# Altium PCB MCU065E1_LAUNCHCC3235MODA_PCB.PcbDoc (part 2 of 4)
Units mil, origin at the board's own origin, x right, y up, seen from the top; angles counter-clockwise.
Board outline 2300 x 4280 mil, 4 copper layers (TOP, GND, PWR, BOTTOM), stack 62 mil thick; 300 components, 199 nets, 970 pads, 475 vias.
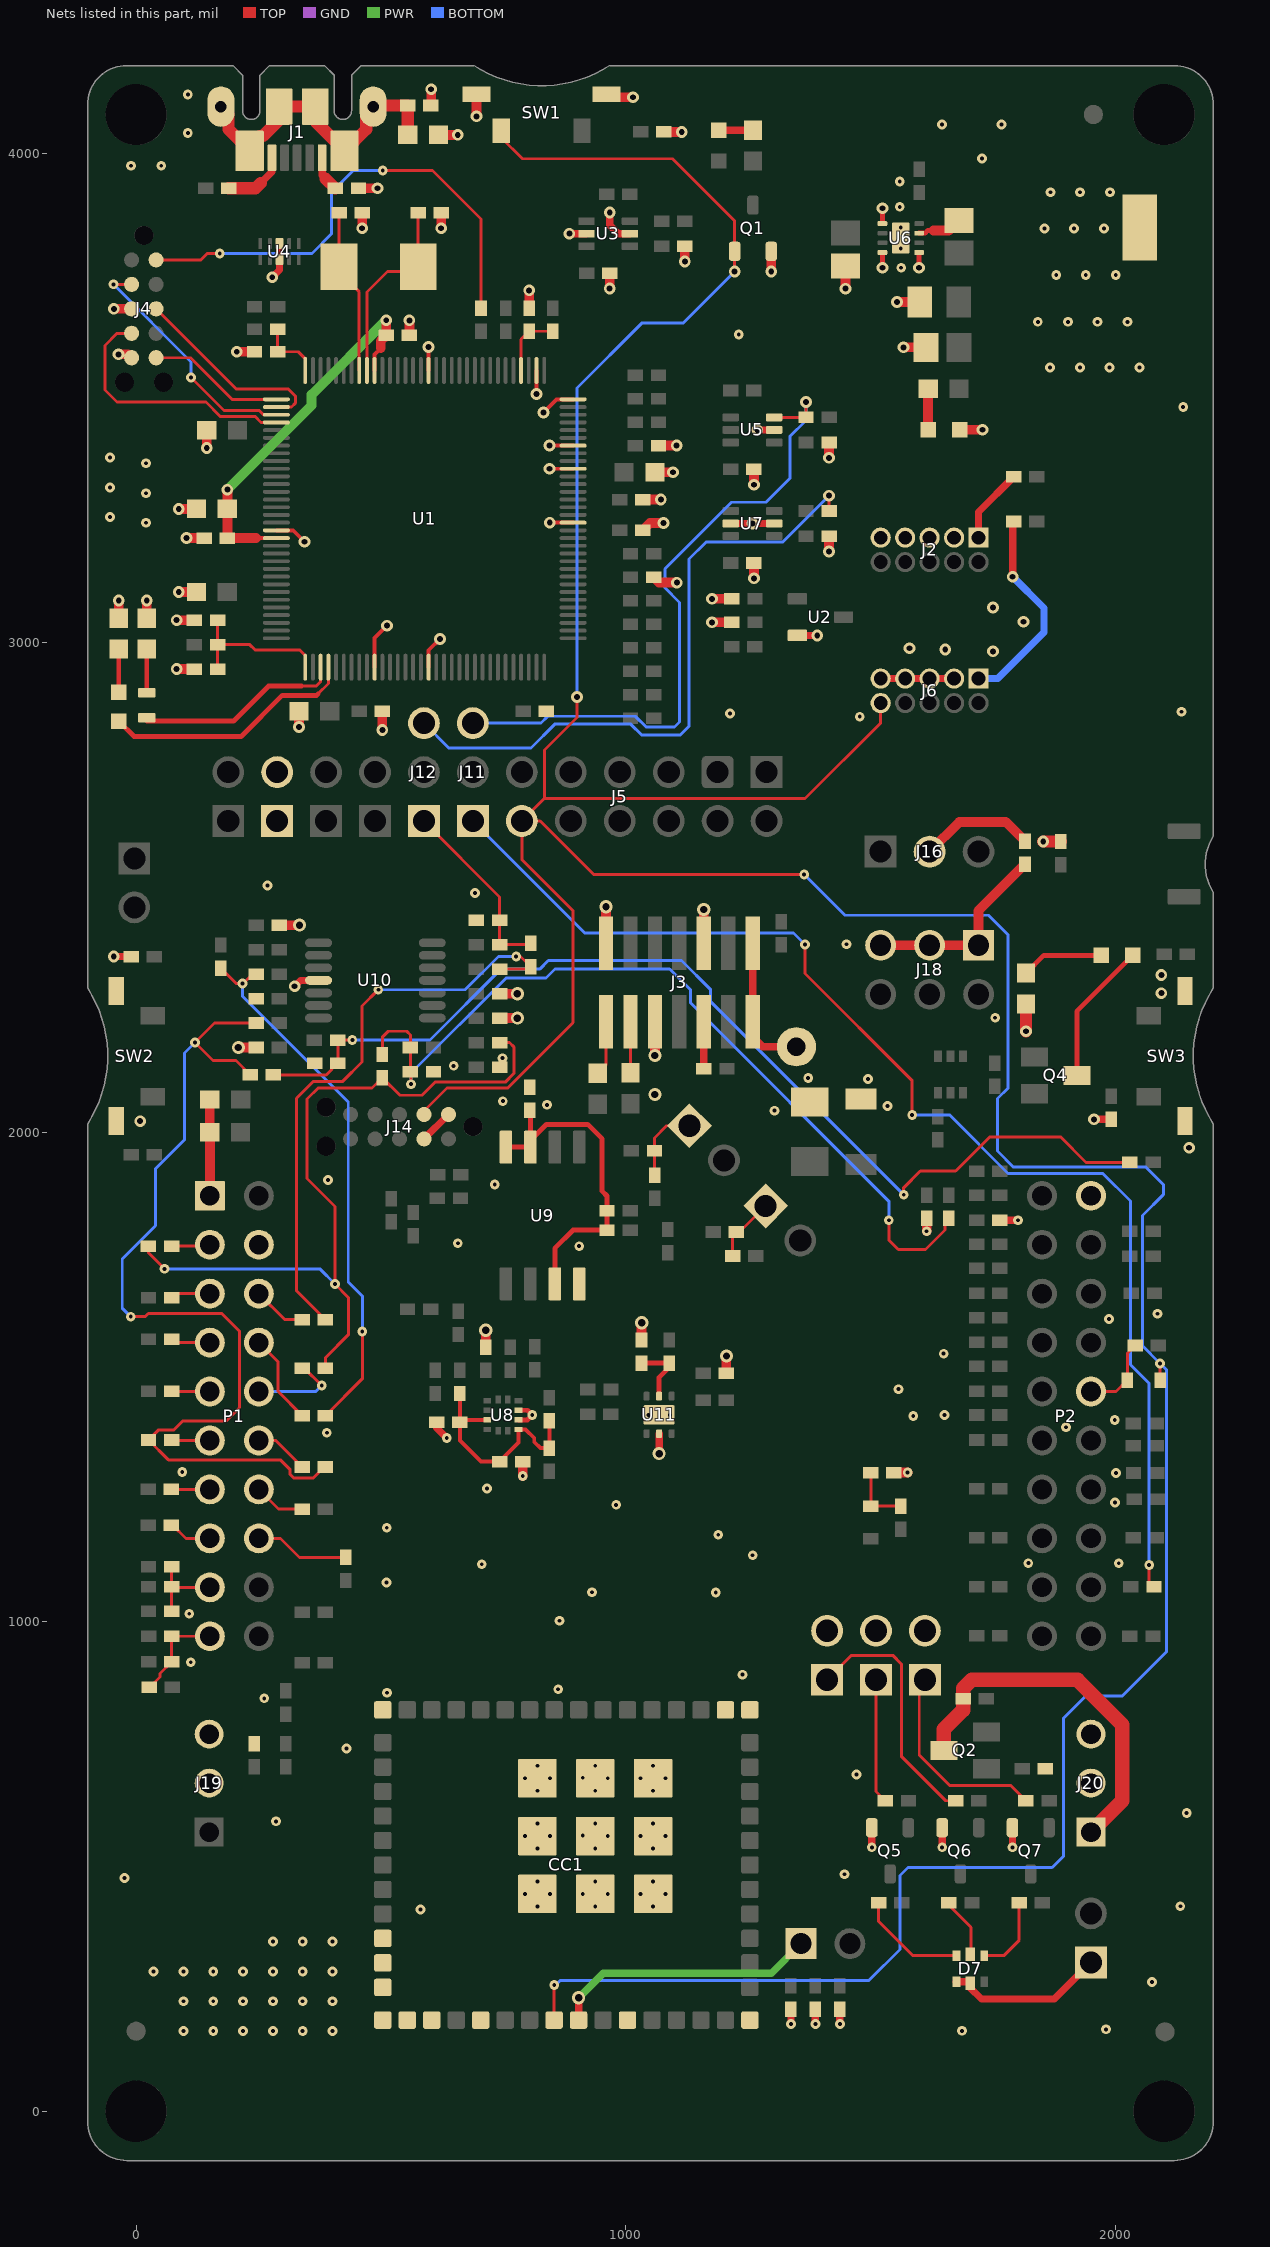
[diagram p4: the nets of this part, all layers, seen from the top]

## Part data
C1: library part CMP-0064930-2, "CAP, CERM, 0.1 uF, 10 V,+/- 10%, X5R, 0402", Cap_Case=0402, Manufacturer="Taiyo Yuden", Supplier Part Number 1=587-1227-1-ND, TempCo=X5R, Tolerance_%=10%, Value1=Unknown, Value2=10V, ValueDisplayed=0.1uF
C2 C5 C6 C7 C12 C14: library part CMP-0860186-1, "CAP, CERM, 0.01 µF, 16 V,+/- 10%, X7R, 0402", Cap_Case=0402, Manufacturer="Samsung Electro-Mechanics", TempCo=X7R, Tolerance_%=10%, Value2=16V, ValueDisplayed=0.01µF
C3 C13 C15 C18: library part CMP-0006347-2, "CAP, CERM, 1 uF, 16 V, +/- 10%, X5R, 0402", Cap_Case=0402, Manufacturer="Taiyo Yuden", Supplier Part Number 1=587-3709-2-ND, TempCo=X5R, Tolerance_%=10%, Value1=Unknown, Value2=16V, ValueDisplayed=1uF
C4 C11: library part CMP-0085851-1, "CAP, CERM, 22 pF, 50 V,+/- 5%, C0G/NP0, 0402", Cap_Case=0402, Manufacturer=Walsin, TempCo=C0G/NP0, Tolerance_%=5%, Value2=50V, ValueDisplayed=22pF
C8 C9 C10 C17: library part CMP-0006758-5, "CAP, CERM, 0.1 uF, 25 V, +/- 10%, X5R, 0603", Cap_Case=0603, Manufacturer=AVX, Supplier Part Number 1=478-1244-1-ND, TempCo=X5R, Tolerance_%=10%, Value1="0.048 ohm", Value2=25V, ValueDisplayed=0.1uF
C16: library part CMP-0006275-2, "CAP, CERM, 2.2 uF, 16 V, +/- 10%, X5R, 0402", Cap_Case=0402, Manufacturer=TDK, Supplier Part Number 1=445-9085-1-ND, TempCo=X5R, Tolerance_%=10%, Value1=Unknown, Value2=16V, ValueDisplayed=2.2uF
C19 C20 C22 C23 C29 C30 C31 C32 C33 C34 C40 C41 C42: library part CMP-0006562-2, "CAP, CERM, 0.1 uF, 10 V, +/- 10%, X5R, 0402", Cap_Case=0402, Manufacturer=MuRata, Supplier Part Number 1=490-1318-1-ND, TempCo=X5R, Tolerance_%=10%, Value1=Unknown, Value2=10V, ValueDisplayed=0.1uF
C21 C36 C37 C38 C39: library part CMP-0006639-2, "CAP, CERM, 0.01 uF, 16 V, +/- 10%, X7R, 0402", Cap_Case=0402, Manufacturer=MuRata, Supplier Part Number 1=490-1313-1-ND, TempCo=X7R, Tolerance_%=10%, Value1=Unknown, Value2=16V, ValueDisplayed=0.01uF
C24 C26: "CAP, CERM, 10 uF, 10 V, +/- 10%, X5R, 0805", Alternate Manufacturer=SAMSUNG, Alternate PartNumber=CL21A106KPFNNNE, Cap_Case=0805, Manufacturer=MuRata, PartNumber=GRM21BR61A106KE19L, Supplier Part Number 1=490-1709-1-ND, TempCo=X5R, Tolerance_%=10%, Value1="0.002 ohm", Value2=10V, ValueDisplayed=10uF
C25: "CAP, CERM, 22 uF, 16 V, +/- 10%, X5R, 0805", Alternate Manufacturer=----, Cap_Case=0805, Manufacturer=TDK, PartNumber=C2012X5R1C226K125AC, Supplier Part Number 1=445-6797-1-ND, TempCo=X5R, Tolerance_%=10%, Value1=Unknown, Value2=16V, ValueDisplayed=22uF
C27 C28: "CAP, CERM, 100 uF, 6.3 V, +/- 20%, X5R, 1206", Alternate Manufacturer=SAMSUNG, Alternate PartNumber=CL31A107MQHNNNE, Cap_Case=1206, Manufacturer=MuRata, PartNumber=GRM31CR60J107ME39L, Supplier Part Number 1=490-4539-1-ND, TempCo=X5R, Tolerance_%=20%, Value1="0.003 ohm", Value2=6.3V, ValueDisplayed=100uF
C35: library part CMP-0006561-2, "CAP, CERM, 0.01 uF, 10 V, +/- 10%, X5R, 0402", Cap_Case=0402, Manufacturer=MuRata, Supplier Part Number 1=GRM155R61A103KA01D-ND, TempCo=X5R, Tolerance_%=10%, Value1=Unknown, Value2=10V, ValueDisplayed=0.01uF
CC1: library part CMP-0085200-1, "SimpleLink Wi-FI and Internet-of-Things Dual Band Module Solution, a Single-Chip Wireless MCU, MON0063A (QFM-63)", Alternate Manufacturer="Texas Instruments"
"CE Logo 1": library part CMP-0074844-1
D1: library part CMP-0002834-1, "LED, Green, SMD", Color=green, Manufacturer=Lumex, Supplier Part Number 1=67-1549-1-ND, Value1=W, Value2=2.2V
D2: library part CMP-0086159-1, "LED, Red, SMD", Color=Red, Manufacturer=Everlight, Power_TotalModule=60mW, Value1=0.06W, Value2=1.95V
D3: "LED, Yellow, SMD", Alternate Manufacturer=Everlight, Alternate PartNumber=19-217/G7C-AN1P2/3T, Color=yellow, Manufacturer="Wurth Elektronik", PartNumber=150060YS75000, Supplier Part Number 1=732-4981-1-ND, Value1=W, Value2=2V
D4 D8: "LED, Red, SMD", Alternate Manufacturer=Everlight, Alternate PartNumber=19-217/R6C-AL1M2VY/3T, Color=red, Manufacturer=Rohm, PartNumber=SML-311UTT86, Supplier Part Number 1=511-1304-1-ND, Value1=W, Value2=1.8V
D5 D6: library part CMP-0081923-1, "Diode, Schottky, 45 V, 0.03 A, SOD-523F", Manufacturer="Comchip Technology", Supplier Part Number 1=641-1006-1-ND, Value1=0.03A, Value2=0.37V
D7: library part CMP-0074720-2, "LED, RGB, TH", Color=RGB, Manufacturer=Everlight, Value2=3.8V
FID1 FID2 FID3: "Fiducial mark.  There is nothing to buy or mount.", Manufacturer=N/A
H1 H2 H3 H4: library part CMP-0077978-1, "Spacer Support, Nylon 66", Manufacturer="Kang Yang"
J1: library part CMP-0055311-1, "Receptacle, USB 2.0, Micro B, 5 Position, R/A, SMT", Color=Black, Current_A=1.8A, Manufacturer=Molex, Supplier Part Number 1=WM11263CT-ND, Voltage_V=30V
J2 J6: "Header, 1.27 mm, 5x2, Gold, TH", Alternate Manufacturer=----, Color=Black, Manufacturer=Samtec, PartNumber=FTSH-105-01-F-D-K, Supplier Part Number 1=FTSH-105-01-F-D-K-ND
J3: "Header, 1.27mm, 7x2, Gold, SMT", Alternate Manufacturer=----, Color=Black, Current_A=3.3A, Manufacturer=Samtec, PartNumber=FTSH-107-01-F-DV, Supplier Part Number 1=FTSH-107-01-F-DV-ND
J4: "Footprint for Tag-Connect TC2050 No-Legs cables", Manufacturer=Tag-Connect, PartNumber=TC2050-IDC-NL-FP
J5: library part CMP-0054806-3, "Header, 2.54 mm, 5x2, Gold, TH", Current_A=3A, Manufacturer="Wurth Elektronik", Supplier Part Number 1=732-2672-ND, Voltage_V=250V
J7 J8 J9 J10 J21 J25: "Header, 2.54 mm, 2x1, Gold, TH", Manufacturer="Wurth Elektronik", PartNumber=61300211121, Supplier Part Number 1=732-5315-ND
J11 J12: library part CMP-0054796-1, "Header, 2.54 mm, 3x1, Gold, TH", Manufacturer="Wurth Elektronik", Supplier Part Number 1=732-5316-ND
J13: library part CMP-0075197-1, "Header, 2.54mm, 2x1, TH", Color=Black, Current_A=2A, Manufacturer=3M, Supplier Part Number 1=3M9447-ND, Voltage_V=1kV
J14: library part CMP-0075101-1, "Footprint for Tag-Connect TC2050 No-Legs cables", Manufacturer=Tag-Connect
J16: "Header, 2.54 mm, 3x1, Gold, TH", Manufacturer="Wurth Elektronik", PartNumber=61300311121, Supplier Part Number 1=732-5316-ND
J18: library part CMP-0054802-2, "Header, 2.54mm, 3x2, Gold, TH", Color=Black, Manufacturer="Wurth Elektronik", Supplier Part Number 1=732-5295-ND
J19 J20: library part CMP-0002338-1, "Header, 100mil, 3x1, Tin, TH", Color=Black, Current_A=3A, Manufacturer="Sullins Connector Solutions", Supplier Part Number 1=S1012E-03-ND, Voltage_V=1.8kV
J22 J23 J24 J26 J27 J28: library part CMP-0054794-1, "Header, 2.54 mm, 2x1, Gold, TH", Manufacturer="Wurth Elektronik", Supplier Part Number 1=732-5315-ND
L1 L2: library part CMP-0003309-1, "Ferrite Bead, 10 ohm @ 100 MHz, 1 A, 0402", Manufacturer=MuRata, Supplier Part Number 1=490-5176-1-ND, Value1="0.025 ohm", Value2=1A, ValueDisplayed="10 ohm"
L3: "Inductor, Wirewound, 2.2 uH, 1 A, 0.143 ohm, SMD", Alternate Manufacturer=----, Manufacturer="Taiyo Yuden", PartNumber=BRC2012T2R2MD, Supplier Part Number 1=587-2905-1-ND, Value1="0.143 ohm", Value2=1A, ValueDisplayed=2.2uH
LBL1: library part CMP-0003625-1, Manufacturer=Brady, PartNumber=THT-14-423-10, Supplier Part Number 1=97C5133
Logo1 "TI Logo 1": library part CMP-0074838-1, "Texas Instrument Corporate Signature"
Logo2: library part CMP-0074840-1, "ESD Susceptible Symbol"
Logo3: library part CMP-0074769-1, "WEEE logo"
Logo4: library part CMP-0074847-1, "FCC_disclaimer"
P1: library part CMP-0003837-2, "Receptacle, 2.54mm, 10x2, Tin, TH", Alternate Manufacturer="Major League Electronics", Alternate PartNumber=CRD-081413-A-G, Manufacturer=Samtec, Supplier Part Number 1=SAM1204-10-ND
P2: library part CMP-0078266-2, "Receptacle, 2.54mm, 10x2, Tin, TH", Alternate Manufacturer="Major League Electronics", Alternate PartNumber=CRD-081413-A-G, Manufacturer=Samtec, Supplier Part Number 1=SAM1204-10-ND
Q1 Q5 Q6 Q7: library part CMP-0000755-1, "MOSFET, N-CH, 50 V, 0.22 A, SOT-23", Alternate Manufacturer=None, Manufacturer="Fairchild Semiconductor", Supplier Part Number 1=BSS138CT-ND, Value2="1.7 nC"
Q2 Q4: library part CMP-0000059-2, "MOSFET, P-CH, -30 V, -1.5 A, SSOT-3", Alternate Manufacturer=None, Manufacturer="Fairchild Semiconductor", Supplier Part Number 1=FDN358PCT-ND, Value1=0, Value2="4 nC"
Q3: library part CMP-0000014-2, "MOSFET, 2-CH, P-CH, -50 V, -0.13 A, AEC-Q101, SOT-363", Alternate Manufacturer=None, Manufacturer="Diodes Inc.", Supplier Part Number 1=BSS84DW-FDICT-ND
R1 R13 R19: "RES, 1.0 k, 5%, 0.063 W, AEC-Q200 Grade 0, 0402", Manufacturer=Vishay-Dale, PartNumber=CRCW04021K00JNED, Power_W=63mW, Supplier Part Number 1=541-1.0KJCT-ND, TempCo="200 ppm/C", Tolerance_%=5%, Value2=0.063W, Value_Code=1k00, ValueDisplayed=1.0k
R2 R4 R6 R7 R8 R9 R10 R34 R37: library part CMP-0026696-1, "RES, 33.0, 1%, 0.1 W, 0402", Manufacturer=Panasonic, Power_W=100mW, Supplier Part Number 1=P33.0LCT-ND, TempCo="100 ppm/C", Tolerance_%=1%, Value2=0.1W, Value_Code=33R0, ValueDisplayed=33.0
R3 R38 R39 R40 R41 R42 R43 R45 R46 R104 R105 R124 R125 R128 R129 R130 R131 R132 R133 R134 R135 R136 R137 R138 R139 R140 R141: library part CMP-0026992-3, "RES, 0, 5%, 0.1 W, AEC-Q200 Grade 0, 0402", Manufacturer=Panasonic, Power_W=100mW, Supplier Part Number 1=P0.0JCT-ND, TempCo="600 ppm/C", Tolerance_%=5%, Value2=0.1W, Value_Code=0000, ValueDisplayed=0
R5: library part CMP-0026824-3, "RES, 100, 5%, 0.063 W, AEC-Q200 Grade 0, 0402", Manufacturer=Vishay-Dale, Power_W=63mW, Supplier Part Number 1=541-100JCT-ND, TempCo="200 ppm/C", Tolerance_%=5%, Value2=0.063W, Value_Code=100R, ValueDisplayed=100
R11: library part CMP-0026905-2, "RES, 330 k, 5%, 0.063 W, AEC-Q200 Grade 0, 0402", Manufacturer=Vishay-Dale, Power_W=63mW, Supplier Part Number 1=541-330KJCT-ND, TempCo="200 ppm/C", Tolerance_%=5%, Value2=0.063W, Value_Code=330k
R12: library part CMP-0026877-2, "RES, 220 k, 5%, 0.063 W, AEC-Q200 Grade 0, 0402", Manufacturer=Vishay-Dale, Power_W=63mW, Supplier Part Number 1=541-220KJCT-ND, TempCo="200 ppm/C", Tolerance_%=5%, Value2=0.063W, Value_Code=220k
R14 R15: library part CMP-0025756-4, "RES, 220, 5%, 0.1 W, AEC-Q200 Grade 0, 0603", Manufacturer=Vishay-Dale, Power_W=100mW, Supplier Part Number 1=541-220GCT-ND, TempCo="200 ppm/C", Tolerance_%=5%, Value2=0.1W, Value_Code=220R, ValueDisplayed=220
R16 R17 R18 R20 R26 R148 R149 R154: library part CMP-0026852-3, "RES, 1.0 k, 5%, 0.063 W, AEC-Q200 Grade 0, 0402", Manufacturer=Vishay-Dale, Power_W=63mW, Supplier Part Number 1=541-1.0KJCT-ND, TempCo="200 ppm/C", Tolerance_%=5%, Value2=0.063W, Value_Code=1k00, ValueDisplayed=1.0k
R21 R22: "RES, 33, 5%, 0.1 W, AEC-Q200 Grade 0, 0603", Alternate Manufacturer=YAGEO, Alternate PartNumber=RC0603JR-0733RL, Manufacturer=Vishay-Dale, PartNumber=CRCW060333R0JNEA, Power_W=100mW, Supplier Part Number 1=541-33GCT-ND, TempCo="200 ppm/C", Tolerance_%=5%, Value2=0.1W, Value_Code=33R0, ValueDisplayed=33
R23: library part CMP-0026946-3, "RES, 51, 5%, 0.063 W, AEC-Q200 Grade 0, 0402", Manufacturer=Vishay-Dale, Power_W=63mW, Supplier Part Number 1=541-51JCT-ND, TempCo="200 ppm/C", Tolerance_%=5%, Value2=0.063W, Value_Code=51R0, ValueDisplayed=51
R24 R29 R49 R52 R143 R155 R156: library part CMP-0026825-5, "RES, 10 k, 5%, 0.063 W, AEC-Q200 Grade 0, 0402", Manufacturer=Vishay-Dale, Power_W=63mW, Supplier Part Number 1=541-10KJCT-ND, TempCo="200 ppm/C", Tolerance_%=5%, Value2=0.063W, Value_Code=10k0, ValueDisplayed=10k
R25: library part CMP-0025951-3, "RES, 100, 1%, 0.063 W, AEC-Q200 Grade 0, 0402", Manufacturer=Vishay-Dale, Power_W=63mW, Supplier Part Number 1=541-100LCT-ND, TempCo="100 ppm/C", Tolerance_%=1%, Value2=0.063W, Value_Code=100R, ValueDisplayed=100
R27: library part CMP-0022457-4, "RES, 4.87 k, 1%, 0.1 W, AEC-Q200 Grade 0, 0603", Manufacturer=Vishay-Dale, Power_W=100mW, Supplier Part Number 1=541-4.87KHCT-ND, TempCo="100 ppm/C", Tolerance_%=1%, Value2=0.1W, Value_Code=4k87, ValueDisplayed=4.87k
R28 R33 R47 R142 R150 R151 R152: library part CMP-0026823-3, "RES, 100 k, 5%, 0.063 W, AEC-Q200 Grade 0, 0402", Manufacturer=Vishay-Dale, Power_W=63mW, Supplier Part Number 1=541-100KJCT-ND, TempCo="200 ppm/C", Tolerance_%=5%, Value2=0.063W, Value_Code=100k
R30 R35: "RES, 270, 5%, 0.1 W, AEC-Q200 Grade 0, 0603", Manufacturer=Vishay-Dale, PartNumber=CRCW0603270RJNEA, Power_W=100mW, Supplier Part Number 1=541-270GCT-ND, TempCo="200 ppm/C", Tolerance_%=5%, Value2=0.1W, Value_Code=270R, ValueDisplayed=270
R31: library part CMP-0082530-1, "RES, 100 k, 5%, 0.1 W, 0603", Manufacturer=Vishay-Dale, Power_W=100mW, Supplier Part Number 1=541-3992-1-ND, TempCo="200 ppm/C", Tolerance_%=5%, Value2=0.1W, Value_Code=100k
R32: "RES, 100, 1%, 0.1 W, 0402", Alternate Manufacturer=YAGEO, Alternate PartNumber=RC0402FR-07100RL, Manufacturer=Panasonic, PartNumber=ERJ-2RKF1000X, Power_W=100mW, Supplier Part Number 1=P100LCT-ND, TempCo="100 ppm/C", Tolerance_%=1%, Value2=0.1W, Value_Code=100R, ValueDisplayed=100
R36 R55 R56: "RES, 100 k, 5%, 0.063 W, AEC-Q200 Grade 0, 0402", Manufacturer=Vishay-Dale, PartNumber=CRCW0402100KJNED, Power_W=63mW, Supplier Part Number 1=541-100KJCT-ND, TempCo="200 ppm/C", Tolerance_%=5%, Value2=0.063W, Value_Code=100k
R44: library part CMP-0026768-2, "RES, 100 k, 0.5%, 0.063 W, AEC-Q200 Grade 0, 0402", Manufacturer=Vishay-Dale, Power_W=63mW, Supplier Part Number 1=541-100KAVCT-ND, TempCo="50 ppm/C", Tolerance_%=0.5%, Value2=0.063W, Value_Code=100k
R51: library part CMP-0026890-5, "RES, 2.2 k, 5%, 0.063 W, AEC-Q200 Grade 0, 0402", Manufacturer=Vishay-Dale, Power_W=63mW, Supplier Part Number 1=541-2.2KJCT-ND, TempCo="200 ppm/C", Tolerance_%=5%, Value2=0.063W, Value_Code=2k20, ValueDisplayed=2.2k
R53 R54 R59 R60 R61 R62 R63 R64 R65 R66 R67 R68 R69 R70 R71 R72 R73 R74 R75 R76 R77 R78 R79 R80 R81 R82 R83 R84 R85 R86 R87 R88 R89 R90 R91 R92 R93 R94 R95 R96 R97 R98 R99 R100 R101 R102 R103 R106 R107 R114 R115 R118 R121: library part CMP-0027004-2, "RES, 0, 5%, 0.063 W, 0402", Manufacturer="Yageo America", Power_W=63mW, Supplier Part Number 1=311-0.0JRCT-ND, TempCo="200 ppm/C", Tolerance_%=5%, Value2=0.063W, Value_Code=0000, ValueDisplayed=0
R57 R58: "RES, 0, 5%, 0.1 W, 0603", Alternate Manufacturer=YAGEO, Alternate PartNumber=RC0603FR-070RL, Manufacturer=Panasonic, PartNumber=ERJ-3GEY0R00V, Power_W=100mW, Supplier Part Number 1=P0.0GCT-ND, TempCo="600 ppm/C", Tolerance_%=5%, Value2=0.1W, Value_Code=0000, ValueDisplayed=0
R108 R110 R116 R119: library part CMP-0026455-2, "RES, 576 k, 1%, 0.063 W, AEC-Q200 Grade 0, 0402", Manufacturer=Vishay-Dale, Power_W=63mW, Supplier Part Number 1=541-576KLCT-ND, TempCo="100 ppm/C", Tolerance_%=1%, Value2=0.063W, Value_Code=576k
R109 R111 R117 R120: library part CMP-0026699-1, "RES, 470, 1%, 0.1 W, AEC-Q200 Grade 0, 0402", Manufacturer=Panasonic, Power_W=100mW, Supplier Part Number 1=P470LCT-ND, TempCo="100 ppm/C", Tolerance_%=1%, Value2=0.1W, Value_Code=470R, ValueDisplayed=470
R112 R113 R122 R123: library part CMP-0026373-2, "RES, 422 k, 1%, 0.063 W, AEC-Q200 Grade 0, 0402", Manufacturer=Vishay-Dale, Power_W=63mW, Supplier Part Number 1=541-422KLCT-ND, TempCo="100 ppm/C", Tolerance_%=1%, Value2=0.063W, Value_Code=422k
R126 R127: library part CMP-0026918-5, "RES, 3.3 k, 5%, 0.063 W, AEC-Q200 Grade 0, 0402", Manufacturer=Vishay-Dale, Power_W=63mW, Supplier Part Number 1=541-3.3KJCT-ND, TempCo="200 ppm/C", Tolerance_%=5%, Value2=0.063W, Value_Code=3k30, ValueDisplayed=3.3k
R144: library part CMP-0026659-1, "RES, 100 k, 1%, 0.1 W, 0402", Manufacturer=Panasonic, Power_W=100mW, TempCo="100 ppm/C", Tolerance_%=1%, Value2=0.1W, Value_Code=100k
R145: library part CMP-0026204-2, "RES, 261, 1%, 0.063 W, AEC-Q200 Grade 0, 0402", Manufacturer=Vishay-Dale, Power_W=63mW, Supplier Part Number 1=541-261LCT-ND, TempCo="100 ppm/C", Tolerance_%=1%, Value2=0.063W, Value_Code=261R, ValueDisplayed=261
R146: library part CMP-0026283-2, "RES, 309, 1%, 0.063 W, AEC-Q200 Grade 0, 0402", Manufacturer=Vishay-Dale, Power_W=63mW, Supplier Part Number 1=541-309LCT-ND, TempCo="100 ppm/C", Tolerance_%=1%, Value2=0.063W, Value_Code=309R, ValueDisplayed=309
R147: library part CMP-0026874-3, "RES, 200, 5%, 0.063 W, AEC-Q200 Grade 0, 0402", Manufacturer=Vishay-Dale, Power_W=63mW, Supplier Part Number 1=541-200JCT-ND, TempCo="200 ppm/C", Tolerance_%=5%, Value2=0.063W, Value_Code=200R, ValueDisplayed=200
R153: library part CMP-0025765-4, "RES, 270, 5%, 0.1 W, AEC-Q200 Grade 0, 0603", Manufacturer=Vishay-Dale, Power_W=100mW, Supplier Part Number 1=541-270GCT-ND, TempCo="200 ppm/C", Tolerance_%=5%, Value2=0.1W, Value_Code=270R, ValueDisplayed=270
SH-J5-1 SH-J5-2 SH-J5-3 SH-J5-4 SH-J5-5 SH-J7 SH-J8 SH-J9 SH-J10 SH-J11 SH-J12 SH-J13 SH-J16 SH-J18 SH-J21 SH-J23 SH-J24 SH-J25: library part CMP-0003623-3, "Shunt, 100mil, Gold plated, Black", Alternate Manufacturer=3M, Alternate PartNumber=969102-0000-DA, Manufacturer=Samtec, PartNumber=SNT-100-BK-G, Supplier Part Number 1=SAM8858-ND
SW1 SW2 SW3: library part CMP-0002231-1, "Switch, SPST-NO,  1 Pos, 0.05A, 12VDC, SMD", CurrentRating_mA=50A, Manufacturer=E-Switch, Supplier Part Number 1=EG4389CT-ND
SW4: library part CMP-0076764-1, "Switch, SPST-NO, Off-Mom, 0.05 A, 12 VDC, SMT", CurrentRating_mA=50A, Manufacturer="Omron Electronic Components", Supplier Part Number 1=SW1022CT-ND
TP1: "TEST POINT.  No entry in BOM.", Manufacturer=N/A
TP2: library part CMP-0055152-1, "Test Point, Miniature, SMT", Manufacturer=Keystone, Supplier Part Number 1=36-5015TR-ND
U1: library part CMP-0077953-1, "MSP432E401YTPDT, PDT0128A (TQFP-128)", Alternate Manufacturer="Texas Instruments", Alternate PartNumber=MSP432E401YTPDTR
U2: library part CMP-0033095-1, "Precision Micropower Shunt Voltage Reference, 0.2% accuracy, 2.5 V, 15 ppm / degC, 15 mA, -40 to 85 degC, 3-pin SOT-23 (DBZ), Green (RoHS & no Sb/Br)", Manufacturer="Texas Instruments", Rating=Catalog, Temp Coeff(Max)(ppm/ degree C)=100, Temp Coeff(Typ)(ppm/ degree C)=15
U3 U5 U7: library part CMP-0051039-3, "Single-Bit Dual-Supply Bus Transceiver with Configurable Voltage Translation and 3-State Outputs, DCK0006A, LARGE T&R", Alternate Manufacturer="Texas Instruments", Alternate PartNumber=SN74LVC1T45DCKT, F @ Nom Voltage(Max)(Mhz)=150, Generic Part Number=SN74LVC1T45, ICC @ Nom Voltage(Max)(mA)=0.004, Operating Temperature Range(C)="-40 to 85", Rating=Catalog, tpd @ Nom Voltage(Max)(ns)=15.5,8,5.8,4.4, Voltage(Nom)(V)=1.8,2.5,3.3,5
U4: library part CMP-0043121-2, "ESD Solution for High-Speed Differential Interface, 4 Channels, -40 to +85 degC,10-pin SON (DQA), Green (RoHS & no Sb/Br)", Breakdown Voltage(Min)(V)=9, Differential Capacitance(pF)=0.05, IO Capacitance(Typ)(pF)=0.8, IO Leakage Current(nA)=10, Manufacturer="Texas Instruments"
U6: "Buck Step Down Regulator with 3 to 17 V Input and 3.3 V Output, -40 to 85 degC, 8-Pin WSON (DSG), Green (RoHS & no Sb/Br)", Manufacturer="Texas Instruments", PartNumber=TPS62162DSGR, Rating=Catalog, Switch Current Limit(Typ)(A)=1.8
U8: library part CMP-0004812-1, "14 Bit, Digital, Triaxial Acceleration Sensor with Intelligent On-Chip Motion-Triggered Interrupt Controller, 12LGA", Manufacturer="Bosch Solar Energy", Supplier Part Number 1=828-1033-1-ND
U9: library part CMP-0004983-1, "ULTRA LOW POWER, 64M-BIT [x 1/x 2/x 4] CMOS MXSMIO (SERIAL MULTI I/O) FLASH MEMORY, SOP-8", Manufacturer="Macronix International Co., LTD", Supplier Part Number 1=1092-1200-ND
U10: library part CMP-0041122-1, "Low Cost, Low Power, Rail-to-Rail Operational Amplifier MicroAmplifier(TM) Series, 2.7 to 5.5 V, -55 to 125 degC, 14-pin SOP (PW14), Green (RoHS & no Sb/Br)", Manufacturer="Texas Instruments", Rating=Catalog, Total Supply Voltage(Max)(+5V is 5, +/-5V is 10)=5.5, Total Supply Voltage(Min)(+5V is 5, +/-5V is 10)=2.7
U11: library part CMP-0013432-6, "High-Accuracy, Low-Power, Digital Temperature Sensor with SMBus and Two-Wire Serial Interface, DRV0006A (WSON-6)", Alternate Manufacturer="Texas Instruments", Alternate PartNumber=TMP116AIDRVT
Y1: "Crystal, 16 MHz, 18 pF, SMD", Alternate Manufacturer=----, Frequency_Fixed=16MHz, Frequency Stability=+/-30ppm, Manufacturer="Abracon Corporation", PartNumber=ABM3-16.000MHZ-D2Y-T, Supplier Part Number 1=535-10638-1-ND
ZZ1 ZZ2 ZZ3: library part CMP-0077238-1, "This Assembly Note will show in the PcbDoc and associated outputs"
ZZ4 ZZ6 ZZ7: library part CMP-0077238-1
ZZ5: library part CMP-0003616-3

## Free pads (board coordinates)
  round 125 hole 125 unplated mask+5: 1(0,0) 1(0,4079) 1(2100,0) 1(2100,4079)

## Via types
v1: diameter 20, hole 8, TOP to BOTTOM, tented both sides, 270 vias
v2: diameter 24, hole 12, TOP to BOTTOM, tented both sides, 142 vias
v3: diameter 19.68, hole 7.87, TOP to BOTTOM, 36 vias
v4: diameter 27, hole 15, TOP to BOTTOM, tented both sides, 23 vias
v5: diameter 19.68, hole 7.87, TOP to BOTTOM, tented bottom, 4 vias

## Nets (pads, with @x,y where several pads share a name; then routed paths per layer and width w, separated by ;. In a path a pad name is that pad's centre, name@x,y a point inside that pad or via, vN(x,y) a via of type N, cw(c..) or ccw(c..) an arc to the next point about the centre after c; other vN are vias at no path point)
ANA_IN1: R65.2 R106.1 R110.1 | length 1216.4
  TOP w6: R65.2@386.62,1617 327.52,1676.1 327.52,2069.33 362.19,2104 422.05,2104 461.67,2143.62 461.67,2257.95 v1(494.77,2291.05) ; R110.1@742.48,2333.14 800.48,2333.14 R106.1@805.86,2338.52 785.12,2359.25 v1(776.37,2359.25)
  BOTTOM w6: v1(494.77,2291.05) 672.09,2291.05 740.29,2359.25 v1(776.37,2359.25)
ANA_IN2: R61.1 R72.2 R115.1 R119.1 | length 1586.7
  TOP w6: R61.1@25.08,1767.51 25.08,1753.77 v1(57.85,1721) ; R72.2@386.62,1518 386.62,1539.38 433.52,1586.28 433.52,1662.56 v1(406.08,1690) 406.08,1848.26 348.95,1905.39 348.95,2067.64 371.94,2090.63 481.97,2090.63 R115.1@502.86,2111.52 538.85,2075.53 583.93,2075.53 610.73,2102.33 754.16,2102.33 771.57,2119.74 771.57,2174.45 762.88,2183.14 R119.1@742.48,2183.14
  BOTTOM w6: v1(57.85,1721) 375.08,1721 v1(406.08,1690)
ANA_IN3: R74.1 R75.2 R114.1 R116.1 | length 1929.3
  TOP w6: v1(-11.03,1623.16) 18.24,1623.16 24.94,1629.86 174.97,1629.86 211.19,1593.64 211.19,1437.27 183.92,1410 95.24,1410 77.31,1392.07 45.98,1392.07 R74.1@25.16,1371.26 65.68,1330.75 294.5,1330.75 314.63,1310.62 314.63,1300.61 321.19,1294.05 362.05,1294.05 384.14,1316.14 R75.2@386.62,1316.14 ; R114.1@233.24,2117.14 203.92,2146.45 156.77,2146.45 v1(120.02,2183.2) 159.96,2223.14 R116.1@245.24,2223.14
  BOTTOM w6: v1(-11.03,1623.16) -28.43,1640.56 -28.43,1741.28 39.47,1809.18 39.47,1925.35 98.83,1984.7 98.83,2162.01 v1(120.02,2183.2)
ANA_IN4: R69.2 R107.1 R108.1 | length 1108.6
  TOP w6: R107.1@173.06,2335.37 204.31,2304.12 v1(217.47,2304.12) 218.99,2304.12 238.01,2323.14 R108.1@245.24,2323.14 ; R69.2@386.62,1421 462,1496.38 v1(462,1593)
  BOTTOM w6: v1(217.47,2304.12) 217.47,2277.62 433.3,2061.79 433.3,1694.24 462,1665.54 v1(462,1593)
CC_NRESET: CC1.35 D6.1 J5.10 J6.10 J14.2 Q1.1 SW1.2 | length 8503.8
  TOP w6: J14.2@588.2,2036.38 588.2,2043.58 634.95,2090.33 759.13,2090.33 892.68,2223.88 892.68,2452.47 788,2557.15 J5.10@788,2635.86 ; SW1.2@745.62,4043.62 745.62,4032.49 789.2,3988.91 1095.48,3988.91 1222.74,3861.65 Q1.1@1222.74,3799.78 v2(1222.74,3758.74) ; J5.10@788.74,2636.6 834.51,2682.38 834.51,2781.04 900.74,2847.27 v2(900.74,2889.04) ; CC1.35@853.9,186.06 853.9,257.38 v1(854.17,257.65) ; v1(1364.81,2526.57) 934.74,2526.57 825.45,2635.86 J5.10@788,2635.86 ; J6.10@1521,2876.86 1521,2836 1366.64,2681.63 833.77,2681.63 J5.10@788,2635.86 ; D6.1@2091.93,1493.18 v1(2091.93,1527.77)
  BOTTOM w6: v1(854.17,257.65) 857.49,257.65 867.17,267.33 1497.1,267.33 1560.28,330.52 1560.28,481.36 1576.89,497.96 1871.52,497.96 1894.92,521.36 1894.92,803.14 1940.39,848.6 2015.14,848.6 2104.69,938.15 2104.69,1515.01 v1(2091.93,1527.77) 2055.87,1563.83 2055.87,1829.81 2098.55,1872.49 2098.55,1893.39 2063.28,1928.66 1792.63,1928.66 1759.89,1961.4 1759.89,2068.65 1780.87,2089.63 1780.87,2404.09 1741.63,2443.33 1448.06,2443.33 v1(1364.81,2526.57) ; v2(900.74,2889.04) 900.74,3520.74 1032.93,3652.93 1116.93,3652.93 v2(1222.74,3758.74)
GND: C1.2 C2.2 C3.1 C4.1 C5.2 C6.2 C7.2 C8.2 C9.2 C10.2 C11.1 C12.2 C13.2 C14.2 C15.2 C16.2 C17.2 C18.2 C19.2 C20.2 C21.2 C22.2 C23.2 C24.2 C25.2 C26.2 C27.2 C28.2 C29.2 C30.2 C31.2 C32.2 C33.2 C34.2 C35.2 C36.2 C37.2 C38.2 C39.2 C40.2 C41.2 C42.2 CC1.1 CC1.2 CC1.16 CC1.25 CC1.26 CC1.27 CC1.28 CC1.29 CC1.30 CC1.32 CC1.38 CC1.43 CC1.55@1056.07,680.16 CC1.56@937.96,680.16 CC1.57@819.84,680.16 CC1.58@1056.07,562.05 CC1.59@937.96,562.05 CC1.60@819.84,562.05 CC1.61@1056.07,443.94 CC1.62@937.96,443.94 CC1.63@819.84,443.94 D4.1 J2.3 J2.5 J2.7 J2.9 J3.5 J3.10 J3.13 J4.3 J4.5 J6.3 J6.5 J6.7 J6.9 J14.1 J14.9 J19.2 J19.3 J20.2 J20.3 J22.1 J22.2 J26.2 J27.2 J28.2 L2.2 P1.22 P2.20 Q1.2 Q5.2 Q6.2 Q7.2 R12.1 R14.1 R15.1 R20.2 R27.1 R31.1 R32.1 R47.1 R52.1 R55.2 R56.2 R105.2 R112.1 R113.1 R122.1 R123.1 R131.2 R132.1 R153.1 R154.1 R155.1 R156.1 SW1.3 SW1.4 SW2.3 SW2.4 SW3.3 SW3.4 TP2.1 U1.10 U1.17 U1.48 U1.55 U1.58 U1.64 U1.66 U1.80 U1.114 U2.2 U3.2 U3.5 U4.3@292.91,3815.67 U4.8@292.91,3782.8 U5.2 U6.1 U6.4 U6.5 U6.9@1562.11,3826.93 U7.2 U7.5 U8.8 U8.9 U9.4 U10.11 U11.2 U11.7@1068.39,1422.6 | length 4083.5
  TOP w7.87: U1.114@286.41,3229.63 320.95,3229.63 v2(344.11,3206.46) ; U1.10@487.19,2950.1 487.19,3009.58 v2(512.55,3034.93) ; U1.17@597.43,2950.1 597.43,2984.64 v2(620.6,3007.8) ; U1.80@597.43,3556.4 v2(597.43,3604.49) ; v2(817.9,3508.3) U1.66@817.9,3556.4 ; v2(831.99,3470.36) 858.97,3497.34 U1.64@892.71,3497.34 ; v2(844.61,3355.61) U1.55@892.71,3355.61 ; v2(844.61,3402.85) U1.58@892.71,3402.85 ; v2(845.02,3245.37) U1.48@892.71,3245.37
  TOP w10: U8.8@781.37,1412.34 789.29,1412.34 799.45,1412.35 v1(809.29,1422.19) 799.44,1432.03 U8.9@781.37,1432.03 ; v2(1524.71,3766.04) U6.4@1524.71,3797.4 ; U6.1@1524.71,3856.45 v2(1524.71,3887.81) ; v2(1599.51,3766.04) U6.5@1599.51,3797.4
  TOP w15: v2(-45.83,2358.95) R155.1@-10.08,2358.95 ; v2@277.93,3746.59 v2(277.93,3746.7) 292.91,3761.68 U4.8@292.91,3782.8 U4.3@292.91,3815.67 ; v2(323.86,2298.14) 335.86,2310.14 U10.11@372.72,2310.14 ; J14.9@588.2,1986.38 J14.1@638.2,2036.38 ; C42.2@614.28,1407.38 614.28,1395.6 v1(634.51,1375.37) ; R123.1@742.48,2133.14 748.57,2139.23 v1(748.57,2151.33) ; v2(884.96,3835.78) U3.5@920.18,3835.78 ; v2(967.61,3878.83) 967.61,3853.03 984.86,3835.78 U3.2@1008.76,3835.78 ; v4(1068.39,1343.45) U11.2@1068.39,1384.22 ; U7.5@1214.86,3243.6 v2(1259.15,3243.6) U7.2@1303.45,3243.6 ; v2(1268.87,3434.78) U5.2@1303.45,3434.78 ; v1(1337.75,177.9) C32.2@1337.75,208.65 ; U2.2@1350.79,3014.92 v2(1391.37,3014.92) ; v1(1387.75,177.9) C33.2@1387.75,208.65 ; v1(1437.75,177.9) C31.2@1437.75,208.65 ; v1(1503.03,539.09) Q5.2@1503.03,579.22 ; J6.9@1521,2926.86 J6.7@1571,2926.86 J6.5@1621,2926.86 J6.3@1671,2926.86 ; v1(1646.65,539.09) Q6.2@1646.65,579.22 ; R55.2@1764.41,1820.27 v1(1801.5,1820.27) ; v1(1790.27,539.09) Q7.2@1790.27,579.22 ; v2(1956.79,2026.36) R156.1@1992.54,2026.36
  TOP w19.9: C36.2@292.48,2423.14 v4(333.86,2423.14)
  TOP w20: v2(-45.57,3682.26) J4.3@-9.21,3682.26 ; v2(-35.95,3589.24) -16.19,3589.24 J4.5@-9.21,3582.26 ; R14.1@-35.48,3050.03 v2(-35.48,3086.39) ; R15.1@21.67,3050.03 v2(21.67,3086.39) ; v2(82.75,2946.17) C2.2@119.12,2946.17 ; v2(82.75,3046.17) R12.1@119.12,3046.17 ; v2(87.01,3103.64) C9.2@123.37,3103.64 ; v2(87.01,3273.49) C17.2@123.37,3273.49 ; v2(102.76,3213.88) C18.2@139.12,3213.88 ; v2(144.24,3397.99) C8.2@144.24,3434.35 ; v2(205.41,3594.58) C1.2@241.77,3594.58 ; v4(208.86,2173.14) R122.1@245.24,2173.14 ; v2(332.71,2827.75) C10.2@332.71,2860.1 ; L2.2@454.25,3928.5 v2(493.25,3928.5) ; v2(461.77,3846.95) C11.1@461.77,3878.32 ; v2(502.94,2821.75) C7.2@502.94,2860.1 ; C16.2@558.18,3628.25 v2(558.18,3658.76) ; C21.2@602.18,4097.66 602.74,4098.22 v2(602.74,4130.84) ; R31.1@617.93,4037.66 v2(656.92,4037.66) ; v2(623.18,3846.95) C4.1@623.18,3878.32 ; v2(695.43,4075.49) SW1.4@695.43,4114.48 ; R131.2@714.29,1560.81 v4(714.29,1595.56) ; C35.2@742.48,2233.14 v4(778.86,2233.14) ; R113.1@742.48,2283.14 v4(778.86,2283.14) ; v1(789.91,1297.81) C41.2@789.91,1327.19 ; C3.1@802.91,3683.64 v2(802.91,3720) ; J3.13@959.79,2386.07 v4(959.79,2460.5) ; SW1.3@961.17,4114.48 v2(1015.16,4114.48) ; v2(967.42,3723.83) C20.2@967.42,3755.19 ; C40.2@1032.39,1575.62 v4@1032.39,1610.24 ; C14.2@1034.95,3229.63 1049.96,3244.64 v2(1077.34,3244.64) ; C15.2@1034.95,3292.62 v2(1071.95,3292.62) ; C5.2@1057.19,3133.64 1068.01,3122.83 v2(1104.58,3122.83) ; v4(1059.79,2156.71) J3.10@1059.79,2225.83 ; R27.1@1059.81,3348.25 v2(1096.81,3348.25) ; R20.2@1067.19,3402.89 v2(1104.2,3402.89) ; R32.1@1078.22,4043.62 v2(1114.58,4043.62) ; v2(1121,3778.83) C19.2@1121,3810.19 ; J3.5@1159.79,2386.07 v4(1159.79,2455.19) ; v2(1176.22,3041.71) C13.2@1217.07,3041.71 ; v2(1176.22,3089.71) C12.2@1217.07,3089.71 ; R132.1@1205.64,1507.79 1205.64,1542.41 v4(1206.01,1542.79) ; v2(1262.11,3131.65) C29.2@1262.11,3163.01 ; v2(1262.11,3322.83) C22.2@1262.11,3354.19 ; v2(1297.54,3758.41) Q1.2@1297.54,3799.78 ; v2(1415.69,3186.65) C30.2@1415.69,3218.01 ; v2(1415.69,3377.83) C23.2@1415.69,3409.19 ; v2(1449.43,3723.48) C26.2@1449.43,3769.84 ; R52.1@1548.19,1304.23 1548.59,1304.63 v1(1576.17,1304.63) ; v2(1554.63,3696.23) C25.2@1600.99,3696.23 ; v2(1567.7,3603.53) C24.2@1614.06,3603.53 ; v1(1615,1797.71) R56.2@1615,1824.02 ; D4.1@1682.96,3435.27 v2(1729.32,3435.27)
  TOP w25: v2(1817.87,2206.35) 1817.87,2261.12 R153.1@1820.08,2263.33 ; v2(1853.17,2593.97) R154.1@1888.8,2593.97
  GND w15: J6.9@1521,2926.86 J6.7@1571,2926.86 J6.5@1621,2926.86 J6.3@1671,2926.86
  other v1: 96.6,163.77 157.5,163.77 218.41,163.77 279.31,163.77 340.22,163.77 401.12,163.77 1687.25,164.24 1981.46,167.2 96.6,224.68 157.5,224.68 218.41,224.68 279.31,224.68 340.22,224.68 401.12,224.68 2075.24,264.11 35.69,285.58 96.6,285.58 157.5,285.58 218.41,285.58 279.31,285.58 340.22,285.58 401.12,285.58 279.31,346.49 340.22,346.49 401.12,346.49 580.71,412.09 2133.21,418.72 -23.93,476.57 1446.98,484 285.82,592.2 2146.2,609.39 1471.57,687.7 429.59,740.78 261.71,843.53 512.23,854.92 862.26,862.01 1238.74,891.81 111.51,917.21 864.63,1001.97 108.47,1016.33 931.59,1060.26 1184.06,1059.52 511.38,1080.11 705.98,1117.46 1822.72,1119.65 2007.5,1119.51 1259.55,1135.85 1189.23,1177.7 511.95,1192 980.64,1238.83 1999.63,1243.39 716.85,1272.18 2001.58,1304.08 94.22,1305.81 389.53,1385.99 1899.65,1397.22 1999.29,1411.93 1587.54,1420.19 1651.5,1422.61 1557.22,1475.05 1649.76,1547.66 1987.33,1618.44 2086.41,1629.12 905.1,1767.18 657.18,1773.21 732.62,1893.08 392.24,1902.32 1304.3,2044.06 1535.1,2053.56 839.2,2056.08 749.13,2063.45 1495.4,2108.76 1373,2110.96 648.76,2135.65 1755.01,2233.97 1451.27,2384.14 692.33,2489 268.62,2503.92 1478.24,2848.96 1213.26,2855.23 2135.59,2859.05 20.32,3245.22 -53.58,3257.12 20.32,3305.42 -53.58,3317.32 20.32,3366.82 -53.58,3378.72 2139.06,3481.6 1866.97,3562.53 1928.37,3562.53 1988.57,3562.53 2049.97,3562.53 1231.17,3629.66 1842.17,3655.71 1903.57,3655.71 1963.77,3655.71 2025.17,3655.71 1879.77,3751.11 1939.97,3751.11 2001.37,3751.11 1562.89,3766.22 1855.97,3846.51 1916.17,3846.51 1977.57,3846.51 1560.03,3890.62 1867.87,3920.41 1928.07,3920.41 1989.47,3920.41 1560.03,3942.62 -10.43,3974.56 51.23,3974.56 1727.87,3989.51 105.51,4041.51 1646.17,4058.71 1767.77,4058.71 105.51,4119.84
  other v2: 2151.27,1968.33 8.24,2022.65 2094.53,2284.13 2094.53,2321.36 1750.64,2982.52 1653,2986.21 1579.77,2988.67 1812.9,3042.96 1750.7,3071.99
  other v3: 819.84,418.34 937.96,418.34 1056.07,418.34 794.25,443.93 845.44,443.93 912.36,443.93 963.55,443.93 1030.47,443.93 1081.66,443.93 819.84,469.53 937.96,469.53 1056.07,469.53 819.84,536.45 937.96,536.45 1056.07,536.45 794.25,562.05 845.44,562.05 963.55,562.05 1030.47,562.05 1081.66,562.05 912.36,563.03 819.84,587.64 937.96,587.64 1056.07,587.64 819.84,654.56 937.96,654.56 1056.07,654.56 794.25,680.16 845.44,680.16 963.55,680.16 1030.47,680.16 1081.66,680.16 912.36,681.14 819.84,705.75 937.96,705.75 1056.07,705.75
  other v4: 1032.77,1610.62 1059.79,2077.04
  other v5: 1046.74,1422.6 1090.04,1422.6 1562.11,3805.27 1562.11,3848.58
IRSTN: J4.10 R25.1 | length 1011.6
  TOP w6: J4.10@40.79,3782.26 132.04,3782.26 145.26,3795.49 v1(170.8,3795.49) ; v1(503.88,3964.57) 605.5,3964.57 704.56,3865.51 R25.1@704.56,3683.64
  BOTTOM w6: v1(170.8,3795.49) 358.99,3795.49 399.49,3835.98 399.49,3920.39 443.67,3964.57 v1(503.88,3964.57)
ITCK: J4.4 U1.100 | length 533.4
  TOP w6: J4.4@-9.21,3632.26 -38.85,3632.26 -63.63,3607.48 -63.63,3516.16 -39.1,3491.64 142.5,3491.64 171.52,3462.62 242.79,3462.62 255.32,3450.1 U1.100@286.41,3450.1
ITDI: J4.8 U1.98 | length 415
  TOP w6: J4.8@40.79,3682.26 204.37,3518.68 310.89,3518.68 325.15,3504.41 325.15,3489.47 317.28,3481.59 U1.98@286.41,3481.59
ITDO: J4.6 U1.97 | length 280.8
  TOP w6: J4.6@40.79,3582.26 110.8,3582.26 195.72,3497.34 U1.97@286.41,3497.34
ITMS: J4.2 U1.99 | length 499
  TOP w6: v1(-46.55,3732.26) J4.2@-9.21,3732.26 ; v1(112.19,3542.1) 179.67,3474.62 251.46,3474.62 260.24,3465.85 U1.99@286.41,3465.85
  BOTTOM w6: v1(-46.55,3732.26) 112.19,3573.52 v1(112.19,3542.1)
LED0: D2.1 U1.3 | length 418.1
  TOP w6: 337.95,2911.3 367.36,2911.3 376.96,2920.89 U1.3@376.96,2950.1
  TOP w10: D2.1@21.67,2839.83 198.92,2839.83 270.38,2911.3 337.95,2911.3
LED1: D1.1 U1.4 | length 519.2
  TOP w6: 371.78,2895.92 392.71,2916.84 U1.4@392.71,2950.1
  TOP w10: D1.1@-35.48,2839.83 -4.23,2808.58 214.47,2808.58 298.5,2892.6 368.47,2892.6 371.78,2895.92
LP_GPIO_01: J11.1 R89.2 | length 2548.5
  TOP w6: v1(1366.2,2383.78) 1366.2,2324.48 1585.44,2105.24 v1(1585.44,2035.13) ; v1(2069.6,1115.98) 2069.6,1081.08 R89.2@2079.41,1071.27
  BOTTOM w6: J11.1@688,2635.26 916.49,2406.78 1343.2,2406.78 v1(1366.2,2383.78) ; v1(1585.44,2035.13) 1662.32,2035.13 1781.47,1915.98 1974.71,1915.98 2031.18,1859.5 2031.18,1525.13 2069.6,1486.71 v1(2069.6,1115.98)
LP_GPIO_02: C37.1 J12.1 R106.2 R111.2 | length 381.2
  TOP w6: J12.1@588,2635.86 588,2635.18 742.48,2480.7 C37.1@742.48,2433.14 R111.2@742.48,2383.14 803.24,2383.14 R106.2@805.86,2385.76
LP_RESET_OUT: D6.2 P2.16 R142.1 | length 161.6
  TOP w6: P2.16@1950.7,1470.26 2002.08,1470.26 D6.2@2025,1493.18 2025,1548.04 R142.1@2041.21,1564.25
NetC1_1: C1.1 R5.1 U1.96 | length 132
  TOP w6: R5.1@289.02,3640.38 C1.1@289.02,3594.58 331.12,3594.58 345.46,3580.24 U1.96@345.46,3556.4
NetC2_1: C2.1 R11.1 R12.2 U1.1 | length 312
  TOP w6: C2.1@166.36,2946.17 R11.1@166.36,2996.17 ; R12.2@166.36,3046.17 R11.1@166.36,2996.17 ; U1.1@345.46,2950.1 345.46,2973.73 333.67,2985.53 242.79,2985.53 232.15,2996.17 R11.1@166.36,2996.17
NetC3_2: C3.2 R23.2 U1.68 | length 134.8
  TOP w6: U1.68@786.41,3556.4 786.41,3619.89 C3.2@802.91,3636.4 R23.2@850.91,3636.4
NetC4_2: C4.2 U1.88 Y1.2 | length 401.9
  TOP w6: U1.88@471.45,3556.4 471.45,3716.69 513.27,3758.52 575.94,3758.52 Y1.2@575.94,3768.32 C4.2@575.94,3878.32
NetC11_2: C11.2 U1.89 Y1.1 | length 339
  TOP w6: C11.2@414.52,3878.32 Y1.1@414.52,3768.32 414.52,3758.16 455.7,3716.98 U1.89@455.7,3556.4
NetC16_1: C16.1 C17.1 C18.1 U1.87 U1.115 | length 793.1
  TOP w7.87: 244.93,3213.88 U1.115@286.41,3213.88 ; U1.87@487.19,3556.4 487.19,3589.3 499.59,3601.7
  TOP w20: v2(186.36,3312.85) C17.1@186.36,3273.49 C18.1@186.36,3213.88 244.93,3213.88 ; 499.59,3601.7 499.59,3616.91 C16.1@510.93,3628.25 v2(510.93,3658.95)
  PWR w20: v2(186.36,3312.85) 358.17,3484.66 358.17,3506.19 ; 358.17,3507.37 358.17,3506.19 ; v2(510.93,3658.95) 358.17,3506.19
NetC21_1: C21.1 J1.6 J1.7 J1.8 J1.9 J1.10 J1.11 R31.2 | length 668.2
  TOP w25: J1.10@173.28,4095.38 188.46,4080.2 188.46,4048.98 232.6,4004.83 232.6,4014.9 253.22,4035.52 258.97,4035.52 292.64,4069.19 292.64,4095.38 366.46,4095.38 366.46,4065.21 425.74,4005.94 J1.6@425.74,4005.59 ; J1.6@425.74,4004.83 470.1,4049.19 470.1,4081.18 J1.7@484.3,4095.38 ; J1.7@484.68,4095 487.34,4097.66 C21.1@554.93,4097.66 R31.2@554.93,4037.66
NetC34_1: C34.1 R38.1 R39.1 U9.3 U9.7 U9.8 | length 687.1
  TOP w10: U9.8@755.4,1969.64 U9.7@805.4,1969.64 U9.7@805.4,1983.16 ; C34.1@804.3,2044.95 805.4,2043.85 U9.7@805.4,1983.16 ; U9.7@805.14,1979.62 805.14,1982.9 U9.7@805.4,1983.16 ; U9.3@855.4,1690.11 855.4,1762.88 892.7,1800.18 R38.1@961.88,1800.18 R39.1@961.88,1839.98 961.88,1869.8 951.98,1879.7 951.98,1986.58 922.46,2016.1 838.34,2016.1 U9.7@805.4,1983.16
NetC38_1: C38.1 R114.2 R117.2 R118.1 | length 2172.9
  TOP w6: R114.2@280.48,2117.14 388.18,2117.14 C38.1@412.29,2141.25 412.29,2187.03 R117.2@411.48,2187.84 416.67,2193.03 421.49,2188.21 v1(441.58,2188.21) ; R114.2@280.77,2114.03 R114.2@282.18,2115.44 ; v1(1568.14,1872.29) 1568.14,1886.62 1602.12,1920.6 1674.36,1920.6 1744.38,1990.62 1888.23,1990.62 1940.58,1938.27 R118.1@2030.34,1938.27
  BOTTOM w6: v1(441.58,2188.21) 600.11,2188.21 745.05,2333.14 824.39,2333.14 842.07,2350.82 1114.36,2350.82 1173.02,2292.16 1173.02,2267.42 v1(1568.14,1872.29)
NetC39_1: C39.1 R115.2 R120.2 R121.1 | length 1746.8
  TOP w6: R115.2@502.86,2158.76 502.86,2194.14 515.07,2206.35 552.64,2206.35 560.24,2198.76 R120.2@560.24,2173.14 C39.1@560.24,2123.14 562.37,2121.01 561.76,2120.4 v1(561.76,2098.14) ; v1(1537.78,1820.27) 1537.78,1779.9 1557.06,1760.62 1612.88,1760.62 1652.68,1800.42 1652.68,1816.7 R121.1@1660,1824.02
  BOTTOM w6: v1(561.76,2098.14) 561.76,2120.87 756.14,2315.25 837.21,2315.25 855.45,2333.5 1089.97,2333.5 1132.36,2291.11 1132.36,2264.47 1537.78,1859.05 v1(1537.78,1820.27)
NetC40_1: C40.1 R125.1 U11.5 | length 133.1
  TOP w10: C40.1@1032.39,1528.38 R125.1@1089.39,1528.38 1089.39,1520.14 1068.39,1499.14 U11.5@1068.39,1460.99
NetC41_1: C41.1 C42.1 R124.2 R129.2 R140.2 U8.3 U8.7 | length 473.5
  TOP w8: R129.2@661.52,1466.32 C42.1@661.52,1407.38 ; U8.3@717.2,1412.34 672.34,1412.34 667.38,1407.38 C42.1@661.52,1407.38 ; R140.2@844.29,1410.56 R124.2@844.29,1354.81 825.67,1354.81 813.29,1367.19 813.29,1375.17 795.8,1392.66 U8.7@781.37,1392.66 781.37,1365.89 C41.1@742.67,1327.19 704.29,1327.19 661.52,1369.95 C42.1@661.52,1407.38
NetCC1_36: CC1.36 J13.1 | length 545.8
  TOP w15: CC1.36@903.9,186.06 v4(903.9,231.69)
  PWR w15: v4(903.9,231.69) 954.3,282.09 1297.9,282.09 J13.1@1358.24,342.43
NetD1_2: D1.2 R14.2 | length 88.1
  TOP w10: D1.2@-35.48,2898.89 R14.2@-35.48,2987.03
NetD2_2: D2.2 R15.2 | length 82.2
  TOP w10: D2.2@21.67,2904.79 R15.2@21.67,2987.03
NetD3_1: D3.1 R30.2 | length 70
  TOP w15: D3.1@1190.14,4047.26 R30.2@1260.14,4047.26
NetD4_2: D4.2 R35.2 | length 83.8
  TOP w20: D4.2@1618,3435.27 R35.2@1618,3519.06
NetD5_1: D5.1 R51.1 R52.2 | length 128.9
  TOP w6: R52.2@1500.95,1304.23 D5.1@1500.95,1236.04 R51.1@1561.65,1236.04
NetD7_1: D7.1 R147.2 | length 161.1
  TOP w6: D7.1@1732.9,317.77 1772.45,317.77 1804.05,349.37 R147.2@1804.05,426.22
NetD7_2: D7.2 R146.2 | length 129.2
  TOP w6: R146.2@1652.56,426.22 1654.87,426.22 1705.42,375.67 1705.42,321.78 D7.2@1704.35,320.72
NetD7_3: D7.3 R145.2 | length 226.3
  TOP w6: R145.2@1516.81,426.22 1516.81,388.07 1587.11,317.77 D7.3@1675.81,317.77
NetD7_5: D7.5 D7.6 J25.1 | length 326.4
  TOP w15: D7.6@1675.81,264.62 1701.4,264.62 D7.5@1704.35,261.66 1704.35,251.83 1727.11,229.07 1875.77,229.07 J25.1@1950.7,304
NetD8_1: D8.1 R153.2 | length 168.4
  TOP w10: R153.2@1817.89,2325.16 1854.14,2361.41 D8.1@1971.32,2361.41
NetD8_2: D8.2 Q4.3 | length 292.7
  TOP w10: Q4.3@1921.92,2116.1 1921.92,2247.04 D8.2@2036.28,2361.41
NetJ1_1: J1.1 L1.1 | length 130.7
  TOP w15: 254.65,3939.36 277.61,3962.32 J1.1@277.61,3990.66
  TOP w25: L1.1@189.3,3928.5 243.77,3928.5 254.64,3939.36
NetJ1_5: J1.5 L2.1 | length 73.5
  TOP w15: J1.5@379.97,3990.66 379.97,3955.25 387.11,3948.11
  TOP w25: 387.11,3948.11 406.72,3928.5 L2.1@407.01,3928.5
NetJ2_1: J2.1 R13.2 | length 153.8
  TOP w15: J2.1@1721,3214.86 1721,3267.03 R13.2@1792.84,3338.87
NetJ3_1: J3.1 J3.2 TP1.1 | length 288.5
  TOP w15: J3.1@1259.79,2386.07 J3.2@1259.79,2225.83 1259.79,2195.06 1280.21,2174.63 TP1.1@1348.79,2174.63
NetJ3_6: J3.6 R19.1 | length 96.5
  TOP w15: R19.1@1159.79,2129.33 J3.6@1159.79,2225.83
NetJ3_12: J3.12 R21.2 | length 104.4
  TOP w6: R21.2@1009.79,2121.44 J3.12@1009.79,2225.83
NetJ3_14: J3.14 R22.2 | length 112.4
  TOP w6: R22.2@942.79,2120.44 959.79,2137.44 J3.14@959.79,2225.83
NetJ6_1: J6.1 R1.2 | length 426.7
  TOP w15: v2(1790.71,3134.82) 1790.71,3245.03 1790.56,3245.19 R1.2@1793.09,3247.73
  BOTTOM w15: J6.1@1721,2926.86 1760.04,2926.86 1854.65,3021.48 1854.65,3070.89 v2(1790.71,3134.82)
NetJ11_3: J11.3 R33.1 U5.3 | length 1364.1
  TOP w6: U5.3@1303.45,3460.37 R33.1@1368.45,3460.37 v2(1368.45,3491.73)
  BOTTOM w6: J11.3@688,2835.86 826.95,2835.86 840.94,2849.85 1019.85,2849.85 1041.97,2827.73 1099.97,2827.73 1110.23,2837.99 1110.23,3082.52 1080.58,3112.18 1080.58,3151.06 1216.53,3287.01 1286.56,3287.01 1335.41,3335.86 1335.41,3421.25 1368.45,3454.29 v2(1368.45,3491.73)
NetJ12_3: J12.3 R37.1 | length 1312.1
  TOP w6: R37.1@1415.69,3269.19 v2(1415.69,3300.55)
  BOTTOM w6: J12.3@588,2835.86 638.62,2785.24 806.62,2785.24 855.08,2833.71 1010.67,2833.71 1032.91,2811.47 1111.59,2811.47 1129.51,2829.39 1129.51,3171.13 1163.92,3205.54 1320.68,3205.54 v2(1415.69,3300.55)
NetJ16_2: J16.2 R49.2 | length 236.3
  TOP w20: J16.2@1621,2573.25 1681.72,2633.98 1776.77,2633.98 R49.2@1815.91,2594.84
NetJ18_1: J18.1 J18.3 J18.5 R49.1 | length 405
  TOP w20: J18.5@1521,2381.86 J18.3@1621,2381.86 J18.1@1721,2381.86 1721,2452.69 R49.1@1815.91,2547.6
NetJ20_1: J20.1 Q2.3 R104.1 | length 759.8
  TOP w30: Q2.3@1650.02,736.93 1650.02,780.22 1689.58,819.78 R104.1@1689.58,842.33 1689.58,864.08 1706.94,881.44 1923.02,881.44 2014.65,789.81 2014.65,634.22 J20.1@1950.7,570.26
NetJ23_1: J23.1 R130.2 R134.2 | length 134.2
  TOP w6: R130.2@1218.48,1747.18 1218.48,1788.63 R134.2@1226.02,1796.18 1232.69,1796.18 J23.1@1286.04,1849.53
NetJ24_1: J24.1 R137.2 R139.2 | length 158.2
  TOP w6: R139.2@1059.3,1912 1058.92,1912.38 R137.2@1058.92,1962.08 1058.92,1988.4 1083.76,2013.23 J24.1@1130.24,2013.23
NetJ26_1: J26.1 R151.1 | length 516.9
  TOP w6: J26.1@1411.5,881.5 1461.29,931.29 1545.75,931.29 1563.27,913.77 1563.27,725.03 1654.08,634.22 R151.1@1674.21,634.22
NetJ27_1: J27.1 R150.1 | length 255.2
  TOP w6: J27.1@1511.5,881.5 1511.5,653.31 R150.1@1530.59,634.22
NetJ28_1: J28.1 R152.1 | length 415.5
  TOP w6: J28.1@1611.5,881.5 1599.84,869.84 1599.84,727.52 1662.18,665.18 1786.87,665.18 R152.1@1817.83,634.22
NetL3_1: L3.1 U6.7 | length 92.4
  TOP w10: U6.7@1599.51,3836.77 1611.82,3836.77 1617.47,3842.42 1629.24,3842.42
  TOP w20: 1629.24,3842.42 1660.32,3842.42 L3.1@1680.99,3863.09
NetP1_1: P1.1 R57.2 R58.2 | length 196.1
  TOP w20: R58.2@150.37,2000.15 R57.2@150.37,2066.7 ; P1.1@150.7,1870.26 R58.2@150.7,1999.82
NetP1_2: P1.2 R61.2 | length 75.6
  TOP w6: R61.2@72.32,1767.51 P1.2@147.95,1767.51
NetP1_3: P1.3 R64.2 | length 81.6
  TOP w6: R64.2@72.41,1662.26 80.41,1670.26 P1.3@150.7,1670.26
NetP1_4: P1.4 R68.2 | length 81.2
  TOP w6: R68.2@72.41,1577.26 79.41,1570.26 P1.4@150.7,1570.26
NetP1_5: P1.5 R71.2 | length 78.7
  TOP w6: R71.2@72.41,1471.26 73.41,1470.26 P1.5@150.7,1470.26
NetP1_6: P1.6 R74.2 | length 78.7
  TOP w6: R74.2@72.41,1371.26 73.41,1370.26 P1.6@150.7,1370.26
NetP1_7: P1.7 R78.2 | length 78.7
  TOP w6: R78.2@72.41,1271.26 73.41,1270.26 P1.7@150.7,1270.26
NetP1_8: P1.8 R82.2 | length 90.2
  TOP w6: R82.2@71.62,1197 75,1197 101.74,1170.26 P1.8@150.7,1170.26
NetP1_9: P1.9 R86.2 R97.2 R102.2 | length 169.7
  TOP w6: R97.2@72.41,1021.26 R102.2@72.41,1071.26 ; R86.2@72.41,1112.26 R102.2@72.41,1071.26 ; P1.9@150.7,1070.26 73.41,1070.26 R102.2@72.41,1071.26
NetP1_10: P1.10 R90.2 R100.2 R103.2 | length 202.3
  TOP w6: R90.2@26.38,866 28,866 49,887 49,894.38 R100.2@72.62,918 R103.2@72.62,970 72.88,970.26 P1.10@150.7,970.26
NetP1_23: P1.23 R65.1 | length 110.7
  TOP w6: P1.23@250.7,1670.26 303.96,1617 R65.1@339.38,1617
NetP1_24: P1.24 R69.1 | length 186
  TOP w6: P1.24@250.7,1570.26 290.21,1530.75 290.21,1470.17 R69.1@339.38,1421
NetP1_25: P1.25 R72.1 | length 184.8
  TOP w6: R72.1@342.79,1518.01 343.64,1518.01 v1(379.24,1482.41)
  BOTTOM w6: P1.25@250.7,1470.26 367.09,1470.26 v1(379.24,1482.41)
NetP1_26: P1.26 R75.1 | length 111.1
  TOP w6: P1.26@250.7,1370.26 285.26,1370.26 R75.1@339.38,1316.14
NetP1_27: P1.27 R79.1 | length 105.4
  TOP w6: P1.27@250.7,1270.26 290.96,1230 R79.1@339.38,1230
NetP1_28: P1.28 R83.1 | length 193.4
  TOP w6: P1.28@250.7,1170.26 295.06,1170.26 333.94,1131.38 R83.1@428,1131.38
